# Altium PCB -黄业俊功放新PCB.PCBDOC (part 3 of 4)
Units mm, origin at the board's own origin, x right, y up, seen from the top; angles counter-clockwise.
Board outline 130 x 100.6 mm, 2 copper layers (Top Layer, Bottom Layer); 47 components, 24 nets, 117 pads, 4 vias.
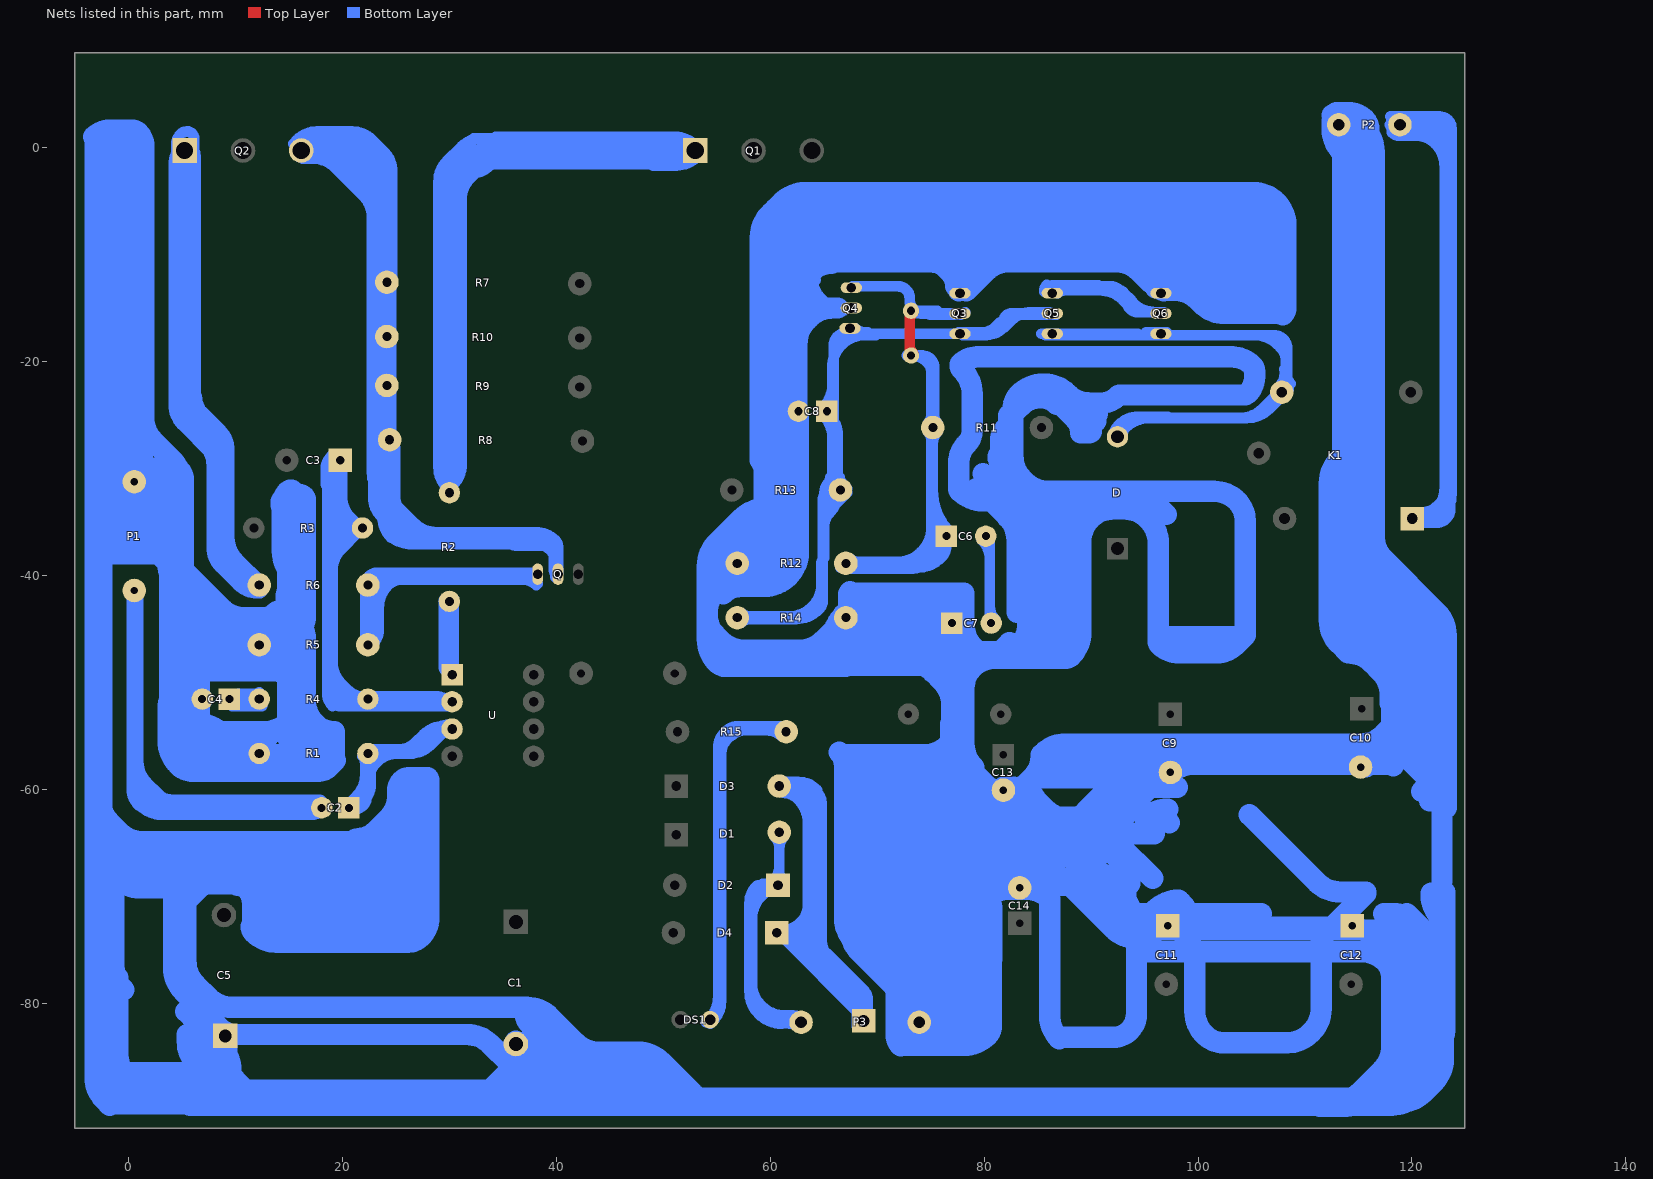
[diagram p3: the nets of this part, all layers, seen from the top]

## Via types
v1: diameter 2.54, hole 0.762, Top Layer to Bottom Layer, 4 vias

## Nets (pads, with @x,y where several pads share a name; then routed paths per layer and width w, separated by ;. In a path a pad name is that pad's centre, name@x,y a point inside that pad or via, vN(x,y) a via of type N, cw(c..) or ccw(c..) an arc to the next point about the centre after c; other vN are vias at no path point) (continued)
GND: (continued)
  Bottom Layer w2: 78.251,-11.434 cw(c81.044,-12.7) 78.582,-10.873 ; 78.251,-11.434 cw(c80.177,-12.954) 78.442,-11.22 78.731,-10.931 cw(c80.899,-13.099) 78.909,-10.766 ; 78.582,-10.873 ccw(c77.798,-7.909) 78.909,-10.766 ; 78.909,-10.766 cw(c80.899,-13.099) 79.788,-10.241 ; 78.909,-10.766 ccw(c77.798,-7.909) 79.788,-10.241 ; 79.788,-10.241 cw(c80.899,-13.099) 80.085,-10.143 ; C13.2@81.788,-60.225 cw(c81.788,-57.837) 80.1,-59.526 ccw(c81.788,-57.837) C13.2@81.788,-60.225 ; 83.058,-67.183 ccw(c81.525,-65.65) 83.595,-66.294 ccw(c81.525,-65.65) 83.63,-66.167 ccw(c81.525,-65.65) 83.654,-66.058 ; 83.058,-67.183 83.058,-65.733 ccw(c83.238,-65.733) 83.111,-65.86 ccw(c83.544,-66.294) 83.058,-65.92 ccw(c83.544,-66.294) 82.931,-66.294 ccw(c82.931,-65.068) 83.058,-66.287 ccw(c82.931,-65.068) 83.474,-66.167 ccw(c82.931,-65.068) 83.654,-66.058 ; 85.874,-62.472 ccw(c87.757,-60.053) 86.535,-62.865 ccw(c87.757,-60.053) 87.06,-63.039 ; 85.874,-62.472 ccw(c87.122,-59.672) 87.122,-62.738 90.17,-62.738 ccw(c90.17,-59.672) 90.178,-62.738 ; 86.006,-62.348 ccw(c87.249,-59.545) 86.969,-62.598 ; 86.006,-62.348 ccw(c87.503,-59.672) 87.458,-62.738 ; 86.931,-63.213 ccw(c88.011,-63.881) 86.767,-63.627 ccw(c88.011,-63.881) 86.741,-63.881 88.138,-63.881 ccw(c88.138,-60.815) 89.024,-63.75 ; 86.931,-63.213 cw(c88.011,-63.881) 86.995,-63.119 cw(c88.011,-63.881) 87.06,-63.039 ; 86.931,-63.213 ccw(c87.376,-60.18) 87.376,-63.246 88.9,-63.246 ccw(c88.9,-60.18) 88.921,-63.246 ; 86.969,-62.598 ccw(c87.249,-59.545) 87.249,-62.611 91.44,-62.611 ; 86.969,-62.598 ccw(c87.884,-59.672) 87.508,-62.715 ; 87.458,-62.738 cw(c88.011,-63.881) 87.508,-62.715 ; 87.508,-62.715 ccw(c87.884,-59.672) 87.884,-62.738 ccw(c87.884,-60.285) 88.663,-62.611 ccw(c87.884,-60.285) 88.711,-62.594 ; 88.711,-62.594 ccw(c88.392,-59.545) 89.178,-62.509 ; 88.711,-62.594 ccw(c87.884,-60.285) 89.313,-62.279 ; 88.921,-63.246 ccw(c88.9,-60.18) 89.773,-63.119 ccw(c88.9,-60.18) 90.259,-62.928 ; 88.921,-63.246 ccw(c91.567,-63.754) 88.876,-63.627 ccw(c91.567,-63.754) 88.873,-63.754 ccw(c88.873,-60.688) 89.024,-63.75 ; 88.921,-63.246 cw(c91.567,-63.754) 88.949,-63.119 cw(c91.567,-63.754) 89.024,-62.865 cw(c91.567,-63.754) 89.072,-62.738 cw(c91.567,-63.754) 89.127,-62.611 cw(c91.567,-63.754) 89.178,-62.509 ; 89.024,-63.75 ccw(c88.873,-60.688) 89.746,-63.627 ccw(c88.873,-60.688) 90.75,-63.113 ; 89.024,-63.75 ccw(c88.138,-60.815) 89.36,-63.627 ccw(c88.138,-60.815) 90.161,-63.119 ccw(c88.138,-60.815) 90.306,-62.983 cw(c90.634,-62.655) 90.259,-62.928 ; 89.178,-62.509 cw(c91.567,-63.754) 89.313,-62.279 ; 89.313,-62.279 cw(c91.567,-63.754) 89.662,-61.849 92.828,-58.683 cw(c94.996,-60.851) 92.993,-58.529 ; 90.178,-62.738 ccw(c90.17,-59.672) 90.645,-62.701 ; 90.178,-62.738 ccw(c90.634,-62.655) 90.259,-62.928 ; 90.178,-62.738 cw(c90.634,-62.655) 90.17,-62.655 ccw(c90.17,-60.614) 90.59,-62.611 ccw(c90.17,-60.614) 90.867,-62.532 ; 90.259,-62.928 ccw(c88.9,-60.18) 90.645,-62.701 ; 90.302,-62.515 ccw(c89.535,-61.849) 90.319,-62.495 ; 90.302,-62.515 cw(c89.535,-61.849) 90.207,-62.611 cw(c89.535,-61.849) 90.027,-62.738 cw(c89.535,-61.849) 89.535,-62.865 85.598,-62.865 cw(c85.598,-61.849) 84.582,-61.849 ccw(c85.852,-61.849) 85.852,-63.119 90.551,-63.119 ccw(c90.551,-60.053) 90.75,-63.113 ; 90.319,-62.495 ccw(c89.789,-61.341) 90.889,-61.976 ccw(c89.789,-61.341) 90.953,-61.849 ccw(c89.789,-61.341) 91.059,-61.341 cw(c91.059,-61.849) 91.522,-61.64 cw(c91.059,-61.849) 91.567,-61.849 90.805,-61.849 ccw(c90.805,-61.976) 90.772,-61.853 ; 90.319,-62.495 cw(c89.789,-61.341) 89.789,-62.611 ccw(c89.789,-61.595) 90.369,-62.429 ; 90.319,-62.495 ccw(c89.535,-61.849) 90.369,-62.429 ; 90.369,-62.429 ccw(c89.789,-61.595) 90.731,-61.976 ccw(c89.789,-61.595) 90.772,-61.853 ; 90.369,-62.429 ccw(c89.535,-61.849) 90.551,-61.849 cw(c91.44,-61.849) 90.562,-61.711 cw(c91.44,-61.849) 91.302,-60.971 cw(c91.44,-61.849) 91.44,-60.96 ccw(c91.44,-61.595) 91.297,-60.976 ccw(c91.44,-61.595) 90.821,-61.452 ccw(c91.44,-61.595) 90.805,-61.595 cw(c89.789,-61.595) 90.772,-61.853 ; 90.645,-62.701 ccw(c90.17,-59.672) 91.043,-62.611 ccw(c90.17,-59.672) 91.43,-62.467 ccw(c90.17,-59.672) 91.568,-62.401 ; 90.645,-62.701 ccw(c88.9,-60.18) 90.768,-62.611 ccw(c88.9,-60.18) 90.867,-62.532 ; 90.75,-63.113 ccw(c90.551,-60.053) 92.719,-62.221 95.033,-59.907 cw(c95.25,-60.124) 95.25,-59.817 ; 90.75,-63.113 ccw(c88.873,-60.688) 90.821,-63.055 ; 90.772,-61.853 ccw(c90.805,-61.976) 90.678,-61.976 91.44,-61.976 ccw(c91.44,-60.706) 91.69,-61.951 ; 90.821,-63.055 ccw(c90.424,-61.849) 91.44,-62.611 ; 90.821,-63.055 ccw(c88.873,-60.688) 91.041,-62.856 93.599,-60.298 cw(c92.001,-60.298) 93.559,-60.655 ; 90.867,-62.532 ccw(c90.17,-60.614) 91.613,-62.057 ccw(c91.613,-59.911) 91.677,-62.056 ; 91.186,-64.157 cw(c89.916,-66.947) 91.802,-64.53 ; 91.186,-64.157 ccw(c91.948,-64.135) 91.198,-64.27 ; 91.198,-64.27 ccw(c91.948,-64.135) 91.948,-64.897 cw(c91.948,-66.167) 92.418,-64.987 ; 91.198,-64.27 cw(c90.297,-67.201) 91.802,-64.53 ; 91.44,-62.611 ccw(c91.44,-61.341) 92.622,-61.805 ; 91.44,-62.611 ccw(c90.424,-61.849) 91.568,-62.401 ; 91.568,-62.401 ccw(c90.17,-59.672) 92.191,-61.978 ; 91.568,-62.401 ccw(c90.424,-61.849) 91.62,-62.277 ccw(c90.424,-61.849) 91.677,-62.056 ; 91.677,-62.056 ccw(c91.613,-59.911) 91.854,-62.043 ccw(c91.613,-59.911) 92.191,-61.978 ; 91.677,-62.056 ccw(c90.424,-61.849) 91.69,-61.951 ; 91.69,-61.951 ccw(c91.44,-60.706) 92.115,-61.782 ccw(c91.44,-60.706) 92.516,-61.381 ccw(c91.44,-60.706) 92.606,-61.208 ; 91.69,-61.951 ccw(c90.424,-61.849) 91.694,-61.849 91.694,-61.595 ccw(c91.694,-60.325) 91.828,-61.588 ccw(c91.694,-60.325) 92.606,-61.208 ; 91.802,-64.53 cw(c90.297,-67.201) 92.418,-64.987 ; 92.191,-61.978 ccw(c91.613,-59.911) 92.622,-61.805 ; 92.191,-61.978 ccw(c90.17,-59.672) 92.338,-61.84 93.367,-60.811 cw(c94.234,-61.678) 93.559,-60.655 ; 92.418,-64.987 cw(c91.948,-66.167) 93.127,-65.695 cw(c91.948,-66.167) 93.218,-66.167 93.218,-70.358 ccw(c94.488,-70.358) 93.472,-71.12 ccw(c94.488,-70.358) 93.726,-71.374 ccw(c94.488,-70.358) 94.488,-71.628 ; 92.606,-61.208 ccw(c91.694,-60.325) 92.71,-61.087 ccw(c91.694,-60.325) 92.957,-60.459 ccw(c91.694,-60.325) 92.964,-60.325 92.964,-58.801 cw(c94.234,-58.801) 92.993,-58.529 ; 92.606,-61.208 ccw(c91.44,-60.706) 92.71,-60.706 92.71,-61.341 cw(c91.44,-61.341) 92.703,-61.475 cw(c91.44,-61.341) 92.622,-61.805 ; 92.622,-61.805 ccw(c91.613,-59.911) 93.091,-61.467 ccw(c91.613,-59.911) 93.131,-61.428 ccw(c92.001,-60.298) 93.559,-60.655 ; 92.993,-58.529 cw(c94.996,-60.851) 93.097,-58.444 ; 55.641,-39.482 cw(c56.896,-40.736) 56.896,-38.962 ccw(c56.896,-40.736) 55.641,-39.482 ; R12.2@56.896,-38.762 ccw(c56.896,-36.374) 58.584,-38.063 cw(c56.896,-36.374) R12.2@56.896,-38.762
NetC2_1: C2.1 R1.1 U.3 | length 90.2
  Bottom Layer w1: C2.1@20.447,-61.722 ccw(c20.447,-59.576) 21.965,-61.093 ccw(c20.416,-59.545) 22.606,-59.545 R1.1@22.606,-57.023 ; C2.1@20.447,-61.468 21.308,-60.607 ccw(c19.4,-58.699) 22.098,-58.699 22.098,-58.268 cw(c24.796,-58.268) 22.888,-56.36 24.946,-56.36 ccw(c24.946,-53.662) 26.854,-55.569 27.531,-54.892 cw(c29.439,-56.8) 29.439,-54.102 U.3@30.099,-54.102 ; C2.1@20.574,-61.849 21.107,-61.849 ccw(c21.107,-60.731) 22.225,-60.731 22.225,-56.515 26.441,-56.515 ccw(c26.441,-55.397) 27.559,-55.397 cw(c28.6,-55.397) 28.6,-54.356 U.3@30.226,-54.356 ; C2.1@21.209,-61.341 21.308,-61.242 ccw(c19.4,-59.334) 22.098,-59.334 22.098,-57.509 ccw(c21.231,-57.509) 21.844,-56.896 21.918,-56.822 ccw(c21.485,-56.388) 22.098,-56.388 cw(c21.791,-56.695) R1.1@22.225,-56.695 ; R1.1@21.971,-56.515 25.298,-56.515 ccw(c25.298,-53.817) 27.206,-55.725 27.912,-55.019 cw(c29.82,-56.927) 29.82,-54.229 U.3@30.099,-54.229 ; 22.352,-59.411 cw(c25.05,-59.411) 23.142,-57.503 23.213,-57.432 cw(c25.121,-59.34) 25.121,-56.642 26.314,-56.642 ; 22.352,-59.309 22.352,-58.903 cw(c25.05,-58.903) 23.142,-56.995 cw(c23.994,-57.846) 23.994,-56.642 26.543,-56.642 27.671,-55.514 ; R1.1@22.606,-56.261 25.171,-56.261 ccw(c25.171,-53.563) 27.079,-55.471 27.559,-54.991 cw(c29.092,-56.524) 29.092,-54.356 U.3@29.718,-54.356 ; R1.1@22.86,-56.642 26.314,-56.642 ; 26.168,-56.255 cw(c27.686,-57.772) 27.686,-55.626 ; 28.238,-54.693 cw(c29.972,-56.428) U.3@29.972,-53.975 ; 28.417,-54.768 cw(c29.718,-56.069) U.3@29.718,-54.229 ; 28.531,-54.781 cw(c29.556,-55.806) 29.556,-54.356 U.3@30.099,-54.356 ; U.3@29.845,-54.229 28.222,-55.852 ; U.3@30.353,-54.483 ccw(c30.353,-56.323) 29.052,-55.022 28.222,-55.852 ; 26.314,-56.642 ccw(c26.314,-53.944) 28.222,-55.852 ; 26.314,-56.642 ccw(c26.314,-53.944) 28.222,-55.852
NetC2_2: C2.2 P1.2 | length 212.5
  Bottom Layer w1: P1.2@0.254,-41.656 0.254,-59.935 ccw(c2.422,-59.935) 0.889,-61.468 ; P1.2@0.508,-41.402 0.508,-60.604 ccw(c1.626,-60.604) 1.626,-61.722 17.78,-61.722 ccw(c17.78,-61.468) C2.2@18.034,-61.468 ; 0.635,-58.039 0.635,-59.207 ccw(c3.333,-59.207) 1.425,-61.115 1.561,-61.251 ccw(c1.778,-61.034) 1.778,-61.341 ; P1.2@0.635,-41.783 cw(c0.328,-42.09) 0.762,-42.09 0.762,-57.683 ccw(c3.46,-57.683) 1.552,-59.591 2.131,-60.17 ccw(c4.039,-58.262) 4.039,-60.96 17.727,-60.96 cw(c17.727,-61.394) C2.2@18.034,-61.087 ; P1.2@0.635,-41.529 0.635,-58.064 ccw(c3.333,-58.064) 1.425,-59.972 2.131,-60.678 ccw(c4.039,-58.77) 4.039,-61.468 11.684,-61.468 ; 0.889,-61.087 ccw(c1.502,-61.087) 1.069,-61.521 1.115,-61.567 ccw(c3.023,-59.659) 3.023,-62.357 17.114,-62.357 ccw(c17.114,-61.056) C2.2@18.034,-61.976 ; 16.383,-61.214 4.674,-61.214 cw(c4.674,-58.516) 2.766,-60.424 1.679,-59.337 cw(c3.587,-57.429) 0.889,-57.429 0.889,-42.576 ccw(c-0.412,-42.576) 0.508,-41.656 0.508,-58.191 ccw(c3.206,-58.191) 1.298,-60.099 1.623,-60.424 ccw(c3.531,-58.516) 3.531,-61.214 C2.2@18.034,-61.214
NetC3_1: C3.1 R3.1 R4.2 U.2 | length 215.3
  Bottom Layer w1: 18.415,-31.496 18.415,-30.055 cw(c20.149,-30.055) 18.923,-28.829 ccw(c19.536,-28.216) 19.536,-29.083 19.536,-32.262 ccw(c22.234,-32.262) 20.326,-34.169 R3.1@21.463,-35.306 ; 18.542,-50.927 19.022,-51.407 ccw(c20.93,-49.499) 20.93,-52.197 U.2@30.099,-52.197 ; 18.542,-49.911 18.542,-50.971 ccw(c20.276,-50.971) 19.05,-52.197 ; 18.669,-35.687 18.895,-35.461 ccw(c16.987,-33.553) 19.685,-33.553 C3.1@19.685,-29.083 ; 18.796,-39.243 18.796,-39.218 cw(c21.494,-39.218) 19.586,-37.31 R3.1@21.336,-35.56 ; 18.796,-36.957 18.796,-31.05 cw(c21.398,-31.05) C3.1@19.558,-29.21 ; 18.923,-49.911 18.923,-50.515 ccw(c20.224,-50.515) 19.304,-51.435 ccw(c19.917,-50.822) 19.917,-51.689 24.257,-51.689 ; 19.177,-50.292 cw(c18.87,-50.599) 19.304,-50.599 19.304,-51.054 ccw(c21.144,-49.214) 21.144,-51.816 U.2@30.48,-51.816 ; C3.1@19.177,-29.337 19.177,-32.664 ccw(c21.875,-32.664) 19.967,-34.572 20.32,-34.925 ; C3.1@19.304,-29.464 ccw(c21.144,-31.304) 18.542,-31.304 18.542,-50.292 ccw(c20.995,-50.292) 19.26,-52.026 ccw(c19.672,-51.615) 19.672,-52.197 23.876,-52.197 ; C3.1@19.558,-29.591 19.558,-33.339 ccw(c22.16,-33.339) 20.32,-35.179 R3.1@21.59,-35.179 ; C3.1@19.939,-29.337 19.939,-32.664 ccw(c22.637,-32.664) 20.729,-34.572 R3.1@21.59,-35.433 ; 20.193,-35.306 19.713,-35.786 ccw(c21.621,-37.694) 18.923,-37.694 18.923,-48.285 ccw(c21.621,-48.285) 19.713,-50.193 20.292,-50.772 ccw(c22.2,-48.864) 22.2,-51.562 28.829,-51.562 ; 20.828,-51.308 28.64,-51.308 cw(c28.64,-53.91) U.2@30.48,-52.07 ; R3.1@21.082,-35.179 ccw(c21.082,-37.325) 19.564,-35.808 19.459,-35.913 ccw(c21.367,-37.821) 18.669,-37.821 18.669,-49.047 ccw(c21.367,-49.047) 19.459,-50.955 ccw(c21.231,-49.184) 21.231,-51.689 R4.2@22.606,-51.689 ; R3.1@21.463,-35.941 19.84,-37.564 ccw(c21.748,-39.472) 19.05,-39.472 19.05,-48.158 ccw(c21.748,-48.158) 19.84,-50.066 20.419,-50.645 ccw(c22.327,-48.737) 22.327,-51.435 R4.2@22.479,-51.435 ; R4.2@21.971,-51.562 19.66,-51.562 cw(c19.66,-50.444) 18.542,-50.444 18.542,-36.297 cw(c19.66,-36.297) 19.66,-35.179 R3.1@22.098,-35.179 ; R4.2@22.225,-51.562 30.226,-51.562 cw(c30.226,-51.943) U.2@30.607,-51.943
NetC4_1: C4.1 R4.1 | length 13.3
  Bottom Layer w1: C4.1@9.398,-51.562 11.938,-51.562 ccw(c11.938,-51.435) R4.1@12.065,-51.435 ; C4.1@9.652,-51.689 11.272,-51.689 cw(c11.272,-52.99) 12.192,-52.07 12.192,-50.927 cw(c11.885,-50.62) 11.885,-51.054 10.287,-51.054 10.011,-51.33 ccw(c10.878,-52.197) 9.652,-52.197 12.446,-52.197 12.446,-51.869 ccw(c12.012,-51.869) R4.1@12.319,-51.562
NetC6_1: C6.1 pad.0@73.152,-15.24 pad.1@73.152,-19.431 Q3.2 Q4.1 R11.1 R12.1 | length 224.7
  Top Layer w1: pad.1@73.025,-19.558 73.025,-15.494 cw(c73.279,-15.494) pad.0@73.279,-15.24 ; 73.025,-18.492 ccw(c74.091,-18.492) pad.1@73.337,-19.246 ; 73.025,-18.492 ccw(c74.091,-18.492) pad.1@73.337,-19.246 ; 73.025,-18.492 ccw(c74.091,-18.492) pad.1@73.337,-19.246 ; 73.025,-18.492 ccw(c74.091,-18.492) pad.1@73.337,-19.246 ; 73.025,-18.492 ccw(c74.091,-18.492) pad.1@73.337,-19.246 ; 73.025,-16.179 cw(c74.091,-16.179) pad.0@73.337,-15.425 ; 73.025,-16.179 cw(c74.091,-16.179) pad.0@73.337,-15.425 ; 73.025,-16.179 cw(c74.091,-16.179) pad.0@73.337,-15.425 ; 73.025,-16.179 cw(c74.091,-16.179) pad.0@73.337,-15.425 ; 73.025,-16.179 cw(c74.091,-16.179) pad.0@73.337,-15.425
  Bottom Layer w1: R12.1@66.548,-39.243 73.787,-39.243 ccw(c73.787,-36.177) 75.27,-38.86 ccw(c73.787,-36.177) 75.955,-38.345 ccw(c74.75,-37.14) 76.326,-37.788 ccw(c74.75,-37.14) 76.454,-37.14 C6.1@76.454,-36.068 ; R12.1@66.802,-39.243 ccw(c67.109,-38.936) 67.109,-39.37 73.025,-39.37 ccw(c73.025,-36.304) 75.193,-38.472 75.565,-38.1 ; R12.1@66.802,-38.735 71.882,-38.735 ccw(c71.882,-35.669) 74.05,-37.837 C6.1@75.692,-36.195 ; R12.1@67.056,-38.735 73.979,-38.735 ccw(c73.979,-36.133) 75.819,-37.973 cw(c76.126,-37.666) 75.692,-37.666 75.692,-35.052 ccw(c76.462,-35.052) C6.1@76.457,-35.822 ; Q4.1@67.691,-12.954 71.907,-12.954 cw(c71.907,-14.072) 73.025,-14.072 73.025,-14.249 ccw(c74.143,-14.249) pad.0@73.625,-15.24 ; 69.731,-39.37 cw(c69.731,-36.187) R12.1@67.48,-38.438 ; 70.231,-39.37 71.247,-39.37 ccw(c71.247,-36.304) 73.415,-38.472 74.159,-37.728 ccw(c71.991,-35.56) 75.057,-35.56 R11.1@75.057,-25.908 ; pad.1@72.771,-19.431 74.193,-19.431 cw(c74.193,-20.549) 75.311,-20.549 R11.1@75.311,-26.289 ; pad.0@72.898,-15.24 75.597,-15.24 ccw(c75.851,-15.24) 75.851,-15.494 77.851,-15.494 cw(c77.724,-15.494) 77.724,-15.621 74.93,-15.621 ; pad.1@73.152,-19.431 cw(c73.152,-21.577) 74.67,-20.06 cw(c73.734,-20.995) 75.057,-20.995 R11.1@75.057,-25.654 ; pad.0@73.152,-15.113 ccw(c74.072,-14.193) 74.072,-15.494 ; pad.1@73.279,-19.431 cw(c73.279,-21.884) 75.013,-20.149 cw(c74.295,-20.868) 75.311,-20.868 R11.1@75.311,-25.4 ; pad.0@73.376,-15.103 ccw(c74.072,-14.678) 74.072,-15.494 ; 74.083,-37.804 cw(c76.454,-40.175) C6.1@76.454,-36.822 ; 74.398,-15.494 cw(c74.398,-13.994) pad.0@73.337,-15.055 ; 74.422,-38.735 ccw(c72.276,-36.589) 75.311,-36.589 75.311,-35.56 ; 75.057,-34.156 ccw(c78.62,-34.156) C6.1@76.1,-36.676 ; 75.057,-31.742 ccw(c81.034,-31.742) C6.1@76.808,-35.968 ; 75.057,-27.917 cw(c76.939,-27.917) R11.1@75.608,-26.586 ; 75.057,-27.304 ccw(c74.042,-27.304) R11.1@74.76,-26.586 ; 75.057,-25.02 cw(c74.042,-25.02) R11.1@74.76,-25.738 ; 75.057,-24.407 ccw(c76.939,-24.407) R11.1@75.608,-25.738 ; R11.1@75.184,-26.162 75.184,-35.077 ccw(c76.302,-35.077) C6.1@76.302,-36.195 ; 75.692,-37.867 cw(c76.769,-37.867) C6.1@76.554,-36.812 ; Q3.2@77.343,-15.494 74.072,-15.494 ; R12.1@67.48,-39.286 cw(c68.811,-40.617) 68.811,-38.735 ccw(c68.811,-40.617) R12.1@67.48,-39.286 ; R12.1@67.48,-39.286 cw(c68.505,-40.311) 68.505,-38.862 ; R12.1@67.48,-39.286 cw(c68.505,-40.311) 68.505,-38.862 ; R12.1@67.48,-39.286 cw(c68.505,-40.311) 68.505,-38.862 ; R12.1@67.48,-38.438 ccw(c68.198,-37.72) 68.198,-38.735 cw(c68.198,-37.72) R12.1@67.48,-38.438 ; R12.1@67.48,-38.438 ccw(c69.424,-36.494) 69.424,-39.243 cw(c69.424,-36.494) R12.1@67.48,-38.438 ; R12.1@67.48,-38.438 ccw(c68.505,-37.413) 68.505,-38.862 ; R12.1@67.48,-38.438 ccw(c68.505,-37.413) 68.505,-38.862 ; R12.1@67.48,-38.438 ccw(c68.505,-37.413) 68.505,-38.862 ; 73.025,-14.301 ccw(c74.091,-14.301) pad.0@73.337,-15.055 ; 73.025,-14.301 ccw(c74.091,-14.301) pad.0@73.337,-15.055 ; 73.025,-14.301 ccw(c74.091,-14.301) pad.0@73.337,-15.055 ; 73.025,-14.301 ccw(c74.091,-14.301) pad.0@73.337,-15.055 ; 73.025,-14.301 ccw(c74.091,-14.301) pad.0@73.337,-15.055 ; 73.025,-14.301 ccw(c74.091,-14.301) pad.0@73.337,-15.055 ; 73.025,-14.301 ccw(c74.091,-14.301) pad.0@73.337,-15.055 ; 73.025,-14.301 ccw(c74.091,-14.301) pad.0@73.337,-15.055 ; 73.025,-14.301 ccw(c74.091,-14.301) pad.0@73.337,-15.055 ; 73.025,-14.301 ccw(c74.091,-14.301) pad.0@73.337,-15.055 ; R11.1@74.76,-26.586 cw(c73.735,-27.611) 75.184,-27.611 ; R11.1@74.76,-26.586 cw(c73.735,-27.611) 75.184,-27.611 ; R11.1@74.76,-25.738 ccw(c73.429,-24.407) 75.311,-24.407 ; R11.1@74.76,-25.738 ccw(c73.429,-24.407) 75.311,-24.407 ; R11.1@74.76,-25.738 ccw(c73.429,-24.407) 75.311,-24.407 ; 75.184,-34.463 ccw(c78.313,-34.463) C6.1@76.1,-36.676 ; 75.184,-34.463 ccw(c78.313,-34.463) C6.1@76.1,-36.676 ; 75.184,-34.463 ccw(c78.313,-34.463) C6.1@76.1,-36.676 ; 75.184,-34.463 ccw(c78.313,-34.463) C6.1@76.1,-36.676 ; 75.184,-34.463 ccw(c78.313,-34.463) C6.1@76.1,-36.676 ; 75.184,-32.049 ccw(c80.727,-32.049) C6.1@76.808,-35.968 ; 75.184,-32.049 ccw(c80.727,-32.049) C6.1@76.808,-35.968 ; 75.184,-32.049 ccw(c80.727,-32.049) C6.1@76.808,-35.968 ; 75.184,-32.049 ccw(c80.727,-32.049) C6.1@76.808,-35.968 ; 75.184,-32.049 ccw(c80.727,-32.049) C6.1@76.808,-35.968 ; 75.184,-27.611 cw(c76.633,-27.611) R11.1@75.608,-26.586 ; 75.184,-27.611 cw(c76.633,-27.611) R11.1@75.608,-26.586 ; 75.311,-25.02 ccw(c76.326,-25.02) R11.1@75.608,-25.738 ; 75.311,-25.02 ccw(c76.326,-25.02) R11.1@75.608,-25.738 ; 75.311,-25.02 ccw(c76.326,-25.02) R11.1@75.608,-25.738 ; 76.327,-37.75 cw(c77.767,-37.75) C6.1@76.792,-36.69 ; 76.327,-37.75 cw(c77.767,-37.75) C6.1@76.792,-36.69 ; 76.327,-37.75 cw(c77.767,-37.75) C6.1@76.792,-36.69
NetC6_2: C6.2 C7.2 | length 19.9
  Bottom Layer w1: C6.2@79.883,-36.195 cw(c79.883,-36.83) 80.518,-36.83 C7.2@80.518,-44.577 ; 80.518,-42.936 ccw(c82.159,-42.936) C7.2@80.999,-44.096 ; C6.2@79.783,-36.676 cw(c78.01,-38.449) 80.518,-38.449 ; C6.2@79.783,-36.676 cw(c78.01,-38.449) 80.518,-38.449 ; C6.2@79.783,-36.676 cw(c78.01,-38.449) 80.518,-38.449 ; C6.2@79.783,-36.676 cw(c78.01,-38.449) 80.518,-38.449 ; C6.2@79.783,-36.676 cw(c78.01,-38.449) 80.518,-38.449
NetC8_1: C8.1 Q3.3 Q4.3 Q5.2 R13.2 R14.1 | length 216.3
  Bottom Layer w1: R14.1@56.769,-43.815 63.627,-43.815 ; R14.1@56.896,-44.069 62.357,-44.069 ccw(c62.357,-41.003) 64.525,-43.171 ccw(c63.627,-42.273) 64.897,-42.273 64.897,-33.528 ; R14.1@56.896,-43.942 61.849,-43.942 ccw(c61.849,-40.876) 64.017,-43.044 ccw(c61.893,-40.92) 64.897,-40.92 64.897,-38.862 64.897,-37.084 ; 60.325,-43.815 61.874,-43.815 ccw(c61.874,-41.117) 63.782,-43.025 63.98,-42.827 ccw(c62.072,-40.919) 64.77,-40.919 64.77,-38.945 cw(c65.637,-38.945) 65.024,-38.332 ; 64.897,-42.545 64.897,-33.02 cw(c66.167,-33.02) 66.04,-31.756 cw(c66.167,-33.02) 66.167,-31.75 66.294,-31.75 cw(c66.294,-31.369) 66.04,-31.653 cw(c66.294,-31.369) 65.913,-31.369 65.913,-18.542 cw(c67.183,-18.542) 66.04,-17.988 cw(c67.183,-18.542) 67.142,-17.273 cw(c67.183,-18.542) 67.183,-17.272 69.088,-17.272 ; 64.897,-35.687 64.897,-33.655 cw(c67.963,-33.655) 65.795,-31.487 R13.2@66.167,-31.115 ; 65.024,-35.687 65.024,-35.535 cw(c67.722,-35.535) 65.814,-33.627 R13.2@67.183,-32.258 ; 65.278,-33.147 cw(c67.424,-33.147) 65.907,-31.629 R13.2@66.294,-31.242 ; C8.1@65.278,-24.765 65.504,-24.991 cw(c63.596,-26.899) 66.294,-26.899 66.294,-32.283 cw(c63.596,-32.283) 65.504,-34.191 ccw(c66.662,-35.349) 65.024,-35.349 65.024,-38.332 ; 65.786,-29.18 ccw(c68.102,-29.18) 66.464,-30.818 ; 65.786,-27.072 ccw(c62.844,-27.072) C8.1@64.924,-24.992 ; 65.786,-22.204 cw(c62.844,-22.204) C8.1@64.924,-24.284 ; 66.167,-28.067 66.167,-29.743 ccw(c68.865,-29.743) 66.957,-31.651 R13.2@67.183,-31.877 ; 69.088,-17.399 80.67,-17.399 ccw(c80.67,-16.281) 81.788,-16.281 cw(c82.575,-16.281) 82.575,-15.494 Q5.2@86.233,-15.494 ; 69.85,-17.526 68.834,-17.526 ccw(c68.834,-20.592) 66.666,-18.424 ccw(c68.79,-20.548) 65.786,-20.548 65.786,-30.681 cw(c65.352,-30.681) 65.659,-30.988 ccw(c67.192,-32.521) 65.024,-32.521 65.024,-38.332 ; Q3.3@77.597,-17.272 79.8,-17.272 ccw(c79.8,-15.538) 81.026,-16.764 81.271,-16.519 cw(c83.439,-18.687) 83.439,-15.621 Q5.2@86.741,-15.621 ; Q3.3@77.978,-17.526 79.883,-17.526 ccw(c79.883,-14.46) 82.051,-16.628 82.55,-16.129 cw(c84.39,-17.969) 84.39,-15.367 Q5.2@86.106,-15.367 ; R14.1@57.32,-44.366 cw(c58.651,-45.697) 58.651,-43.815 ccw(c58.651,-45.697) R14.1@57.32,-44.366 ; R14.1@57.32,-44.366 cw(c58.038,-45.084) 58.038,-44.069 ; R14.1@57.32,-44.366 cw(c58.345,-45.391) 58.345,-43.942 cw(c58.345,-42.493) R14.1@57.32,-43.518 ; R14.1@57.32,-44.366 cw(c58.038,-45.084) 58.038,-44.069 ; R14.1@57.32,-44.366 cw(c58.038,-45.084) 58.038,-44.069 ; R14.1@57.32,-44.366 cw(c58.038,-45.084) 58.038,-44.069 ; R14.1@57.32,-43.518 ccw(c58.038,-42.8) 58.038,-43.815 cw(c58.038,-42.8) R14.1@57.32,-43.518 ; R14.1@57.32,-43.518 ccw(c58.651,-42.187) 58.651,-44.069 ; R14.1@57.32,-43.518 ccw(c58.651,-42.187) 58.651,-44.069 ; R14.1@57.32,-43.518 ccw(c58.651,-42.187) 58.651,-44.069 ; R14.1@57.32,-43.518 ccw(c58.651,-42.187) 58.651,-44.069 ; C8.1@64.924,-24.992 cw(c62.538,-27.378) 65.913,-27.378 ccw(c62.538,-27.378) C8.1@64.924,-24.992 ; C8.1@64.924,-24.284 ccw(c62.538,-21.898) 65.913,-21.898 cw(c62.538,-21.898) C8.1@64.924,-24.284 ; 65.616,-30.818 ccw(c64.898,-30.1) 65.913,-30.1 cw(c64.898,-30.1) 65.616,-30.818 ; 65.616,-30.818 ccw(c64.591,-29.793) 66.04,-29.793 ; 65.616,-30.818 ccw(c64.591,-29.793) 66.04,-29.793 ; 65.616,-30.818 ccw(c64.591,-29.793) 66.04,-29.793 ; 66.04,-29.793 ccw(c67.489,-29.793) 66.464,-30.818 ; 66.04,-29.793 ccw(c67.489,-29.793) 66.464,-30.818 ; 66.04,-29.793 ccw(c67.489,-29.793) 66.464,-30.818 ; 66.464,-30.818 cw(c67.795,-29.487) 65.913,-29.487 ccw(c67.795,-29.487) 66.464,-30.818 ; Q4.3@67.937,-16.891 ccw(c68.857,-15.971) 68.857,-17.272 cw(c68.857,-15.971) Q4.3@67.937,-16.891 ; Q4.3@67.937,-16.891 ccw(c69.163,-15.665) 69.163,-17.399 ; Q4.3@67.937,-16.891 ccw(c69.163,-15.665) 69.163,-17.399 ; Q4.3@67.937,-16.891 ccw(c69.163,-15.665) 69.163,-17.399
NetD1_1: D1.1 D2.2 P3.3 | length 104.7
  Bottom Layer w1: 58.039,-76.835 58.039,-78.486 ccw(c61.105,-78.486) 58.937,-80.654 59.173,-80.89 ccw(c61.341,-78.722) 61.341,-81.788 ; 58.039,-76.581 58.039,-77.851 ccw(c61.105,-77.851) 58.937,-80.019 59.935,-81.017 ccw(c62.103,-78.849) P3.3@62.103,-81.915 ; 58.039,-73.787 58.039,-72.009 cw(c61.105,-72.009) 58.937,-69.841 59.585,-69.193 cw(c60.452,-70.06) D2.2@60.452,-68.834 ; 58.293,-74.295 58.293,-78.297 ccw(c60.895,-78.297) 59.055,-80.137 59.789,-80.871 ccw(c61.697,-78.963) 61.697,-81.661 ; 59.14,-69.638 cw(c59.874,-70.371) D2.2@60.401,-69.478 ; 59.532,-69.627 cw(c60.833,-70.928) D2.2@60.833,-69.088 ; D2.2@60.579,-68.58 59.101,-70.058 ccw(c61.052,-72.009) 58.293,-72.009 58.293,-77.089 ccw(c58.6,-77.396) 58.166,-77.396 58.166,-77.978 ccw(c61.232,-77.978) 59.064,-80.146 59.173,-80.255 ccw(c61.341,-78.087) 61.341,-81.153 62.072,-81.153 cw(c62.072,-82.454) 62.992,-81.534 63.156,-81.698 cw(c62.939,-81.915) 63.246,-81.915 ccw(c63.246,-82.222) P3.3@63.029,-82.005 ; D2.2@60.706,-68.961 58.981,-68.961 ccw(c58.981,-69.395) 58.674,-69.088 ccw(c60.207,-70.621) 58.039,-70.621 58.039,-78.893 ccw(c61.043,-78.893) 58.166,-79.757 ccw(c61.043,-78.893) 58.293,-80.102 ccw(c61.043,-78.893) 58.919,-81.017 ccw(c61.087,-78.849) 61.087,-81.915 ; D2.2@60.833,-68.834 D1.1@60.833,-64.008 ; 59.257,-68.961 cw(c59.257,-70.41) 60.282,-69.385 ccw(c59.257,-70.41) 59.257,-68.961 ; 59.257,-68.961 ccw(c59.257,-67.512) D2.2@60.282,-68.537 ; 59.257,-68.961 ccw(c59.257,-67.512) D2.2@60.282,-68.537 ; 59.284,-68.834 cw(c59.284,-69.989) D2.2@60.22,-69.312 ; 59.284,-68.834 cw(c59.284,-69.989) D2.2@60.22,-69.312 ; 59.284,-68.834 cw(c59.284,-69.989) D2.2@60.22,-69.312 ; 59.564,-68.834 ccw(c59.564,-67.819) D2.2@60.282,-68.537 ; 59.564,-68.834 ccw(c59.564,-67.819) D2.2@60.282,-68.537 ; 59.564,-68.834 ccw(c59.564,-67.819) D2.2@60.282,-68.537 ; D2.2@60.282,-68.537 ccw(c58.951,-67.206) 60.833,-67.206 ; D2.2@60.282,-68.537 ccw(c58.951,-67.206) 60.833,-67.206 ; D2.2@60.282,-68.537 ccw(c58.951,-67.206) 60.833,-67.206 ; D2.2@60.282,-68.537 ccw(c58.951,-67.206) 60.833,-67.206 ; D2.2@60.282,-68.537 ccw(c58.951,-67.206) 60.833,-67.206 ; D1.1@60.409,-64.432 cw(c59.384,-65.457) 60.833,-65.457 ; D1.1@60.409,-64.432 cw(c59.384,-65.457) 60.833,-65.457 ; D1.1@60.409,-64.432 cw(c59.384,-65.457) 60.833,-65.457 ; D1.1@60.409,-64.432 cw(c59.384,-65.457) 60.833,-65.457 ; D1.1@60.409,-64.432 cw(c59.384,-65.457) 60.833,-65.457 ; 60.833,-67.819 ccw(c61.848,-67.819) D2.2@61.13,-68.537 ; 60.833,-67.819 ccw(c61.848,-67.819) D2.2@61.13,-68.537 ; 60.833,-67.819 ccw(c61.848,-67.819) D2.2@61.13,-68.537 ; 60.833,-67.819 ccw(c61.848,-67.819) D2.2@61.13,-68.537 ; 60.833,-67.819 ccw(c61.848,-67.819) D2.2@61.13,-68.537 ; 60.833,-65.457 cw(c62.282,-65.457) D1.1@61.257,-64.432 ; 60.833,-65.457 cw(c62.282,-65.457) D1.1@61.257,-64.432 ; 60.833,-65.457 cw(c62.282,-65.457) D1.1@61.257,-64.432 ; 60.833,-65.457 cw(c62.282,-65.457) D1.1@61.257,-64.432 ; 60.833,-65.457 cw(c62.282,-65.457) D1.1@61.257,-64.432
NetD3_1: D3.1 D4.2 P3.1 | length 234.4
  Bottom Layer w1: D4.2@60.198,-73.66 60.858,-73.66 cw(c60.858,-76.358) 62.766,-74.45 65.061,-76.745 ; D4.2@60.198,-73.533 61.112,-73.533 cw(c61.112,-76.231) 63.02,-74.323 63.776,-75.079 ccw(c64.643,-74.212) 64.643,-75.438 ; D4.2@60.325,-73.279 63.119,-73.279 cw(c63.119,-74.549) 63.516,-73.343 cw(c63.119,-74.549) 64.262,-73.995 ; D4.2@60.452,-73.787 62.348,-73.787 ; D4.2@60.452,-73.279 60.706,-73.279 ccw(c60.706,-70.213) 62.874,-72.381 ccw(c61.363,-70.87) 63.5,-70.87 63.5,-63.119 ccw(c60.434,-63.119) 62.602,-60.951 62.515,-60.864 ccw(c61.214,-62.165) 61.214,-60.325 D3.1@60.579,-59.69 ; D4.2@60.706,-73.66 61.874,-73.66 cw(c61.874,-76.358) 63.782,-74.45 65.123,-75.791 ; D3.1@60.833,-59.563 62.782,-59.563 cw(c62.782,-61.297) 64.008,-60.071 ; D4.2@60.96,-73.533 ccw(c61.267,-73.533) 61.05,-73.75 68.49,-81.19 cw(c68.273,-81.407) P3.1@68.58,-81.407 ; D4.2@60.96,-73.406 ccw(c61.267,-73.099) 61.267,-73.533 62.646,-73.533 ccw(c62.646,-72.697) 63.237,-73.288 ccw(c61.069,-71.12) 64.135,-71.12 64.135,-61.127 ccw(c63.119,-61.127) 63.837,-60.408 ccw(c62.103,-62.143) 62.103,-59.69 cw(c62.103,-58.464) 61.236,-59.331 61.214,-59.309 62.549,-59.309 ; D4.2@61.087,-73.152 62.611,-73.152 cw(c62.611,-74.422) 63.881,-74.422 ; D4.2@61.088,-73.088 ccw(c62.348,-72.302) 62.348,-73.787 ; D3.1@61.214,-60.071 62.125,-60.071 ; D3.1@61.35,-59.994 cw(c62.549,-60.701) 62.549,-59.309 ; D3.1@61.411,-59.529 ccw(c62.125,-59.33) 62.125,-60.071 ; 61.721,-73.533 ccw(c61.721,-74.548) 61.003,-73.83 cw(c62.334,-75.161) 62.334,-73.279 ; 61.721,-73.279 cw(c61.721,-72.264) 61.003,-72.982 ccw(c62.334,-71.651) 62.334,-73.533 ; 61.975,-59.563 cw(c61.975,-58.548) D3.1@61.257,-59.266 ; 62.588,-59.563 ccw(c62.588,-61.445) D3.1@61.257,-60.114 ; 63.246,-59.436 cw(c63.246,-60.356) 63.896,-59.705 cw(c62.401,-61.201) 64.516,-61.201 64.516,-74.308 ccw(c67.551,-74.308) 65.405,-76.454 ; 63.754,-73.025 ccw(c63.141,-72.412) 64.008,-72.412 64.008,-62.611 ccw(c61.555,-62.611) 63.29,-60.877 62.738,-60.325 ccw(c62.125,-60.938) 62.125,-60.071 ; 64.262,-75.184 ccw(c63.036,-73.958) 64.77,-73.958 64.77,-61.245 ccw(c63.469,-61.245) 64.389,-60.325 ccw(c62.856,-61.858) 62.856,-59.69 D3.1@60.833,-59.69 62.992,-59.69 cw(c62.992,-60.96) 64.262,-60.96 64.262,-73.995 ; 64.262,-74.803 64.262,-75.819 ccw(c65.532,-75.819) 65.532,-77.089 ; 64.389,-74.803 64.389,-74.549 ccw(c63.119,-74.549) 64.262,-73.995 ; 64.77,-73.406 64.77,-73.914 ccw(c67.836,-73.914) 65.668,-76.082 ; 64.984,-76.064 64.262,-75.342 ccw(c62.961,-75.342) 63.881,-74.422 ; 65.269,-76.191 cw(c67.393,-74.067) 64.389,-74.067 64.389,-72.136 64.389,-60.071 ccw(c62.549,-61.911) 62.549,-59.309 ; 65.786,-76.962 65.823,-76.999 ccw(c66.04,-76.782) 66.04,-77.089 67.682,-78.731 cw(c65.514,-80.899) 68.58,-80.899 68.58,-81.026 68.58,-80.137 ccw(c65.514,-80.137) 67.682,-77.969 63.627,-73.914 cw(c62.707,-74.834) 64.008,-74.834 64.008,-74.93 cw(c64.008,-77.076) 65.526,-75.559 68.707,-78.74 cw(c67.787,-79.66) 69.088,-79.66 69.088,-81.862 ccw(c69.522,-81.862) 69.215,-82.169 68.072,-82.169 68.072,-81.28 ccw(c65.006,-81.28) 67.174,-79.112 64.779,-76.717 cw(c66.947,-74.549) 63.881,-74.549 63.881,-74.422 ; D3.1@61.257,-60.114 cw(c62.282,-61.139) 62.282,-59.69 ; D3.1@61.257,-60.114 cw(c62.282,-61.139) 62.282,-59.69 ; D3.1@61.257,-60.114 cw(c62.282,-61.139) 62.282,-59.69 ; D3.1@61.257,-60.114 cw(c62.282,-61.139) 62.282,-59.69 ; D3.1@61.257,-60.114 cw(c62.282,-61.139) 62.282,-59.69 ; D3.1@61.257,-60.114 cw(c62.282,-61.139) 62.282,-59.69 ; D3.1@61.257,-59.266 ccw(c62.282,-58.241) 62.282,-59.69 ; D3.1@61.257,-59.266 ccw(c62.282,-58.241) 62.282,-59.69 ; D3.1@61.257,-59.266 ccw(c62.282,-58.241) 62.282,-59.69 ; D3.1@61.257,-59.266 ccw(c62.282,-58.241) 62.282,-59.69 ; D3.1@61.257,-59.266 ccw(c62.282,-58.241) 62.282,-59.69 ; D3.1@61.257,-59.266 ccw(c62.282,-58.241) 62.282,-59.69 ; 62.348,-73.787 cw(c62.348,-75.955) 63.881,-74.422
NetD_1: D.1 K1.5 Q5.3 Q6.3 | length 149.7
  Bottom Layer w1: 85.344,-17.399 94.361,-17.399 ; Q5.3@85.725,-17.526 Q6.3@96.774,-17.526 ; Q5.3@86.36,-17.526 107.061,-17.526 cw(c107.061,-18.796) 108.331,-18.796 K1.5@108.331,-22.606 ; D.1@92.075,-27.178 cw(c93.915,-27.178) 92.614,-25.877 cw(c94.379,-27.642) 94.379,-25.146 97.155,-25.146 ccw(c97.462,-24.839) 97.462,-25.273 104.521,-25.273 ; D.1@92.202,-27.178 D.1@92.202,-27.028 ; D.1@92.329,-27.051 93.209,-26.171 ; 95.123,-17.272 Q6.3@97.053,-17.272 ; Q6.3@96.266,-17.526 Q6.3@96.266,-17.399 ; 98.171,-25.273 103.886,-25.273 ccw(c103.886,-22.207) 106.054,-24.375 107.755,-22.674 ccw(c106.671,-21.59) 108.204,-21.59 ; 101.346,-17.526 105.283,-17.526 cw(c105.283,-20.592) 107.451,-18.424 107.696,-18.669 cw(c106.47,-19.895) 108.204,-19.895 108.204,-21.59 ; 104.648,-17.526 105.677,-17.526 cw(c105.677,-20.561) 107.823,-18.415 cw(c106.597,-19.641) 108.331,-19.641 108.331,-19.939 ; 106.746,-23.683 cw(c108.204,-25.141) K1.5@108.204,-23.079 ; 107.188,-23.876 107.306,-23.758 ccw(c105.138,-21.59) 108.204,-21.59 ; K1.5@107.379,-23.685 ccw(c106.656,-22.963) K1.5@107.631,-22.658 ; K1.5@107.497,-23.567 ccw(c106.958,-23.029) K1.5@107.655,-22.721 ; K1.5@107.832,-22.008 ccw(c107.016,-20.977) 108.331,-20.977 ; K1.5@108.077,-22.479 108.077,-22.352 K1.5@108.204,-22.352 ; 108.204,-20.32 108.204,-21.59 ; 108.331,-19.05 108.331,-20.977 ; K1.5@108.458,-22.606 106.689,-24.375 cw(c104.521,-22.207) 104.521,-25.273 ; 93.209,-26.171 ccw(c93.857,-26.819) 92.951,-26.954 cw(c93.857,-26.819) 93.209,-26.171 ; 93.209,-26.171 cw(c95.377,-28.339) 95.377,-25.273 104.521,-25.273 ; 104.521,-25.273 ccw(c104.521,-22.514) 106.472,-24.465 107.179,-23.758 ccw(c105.011,-21.59) 108.077,-21.59 ccw(c107.464,-20.977) 108.331,-20.977 ; K1.5@107.78,-22.055 ccw(c106.449,-20.724) 108.331,-20.724 ; K1.5@107.78,-22.055 ccw(c106.755,-21.03) 108.204,-21.03 ; K1.5@107.78,-22.055 ccw(c106.755,-21.03) 108.204,-21.03 ; K1.5@107.78,-22.055 ccw(c106.449,-20.724) 108.331,-20.724 ; K1.5@107.78,-22.055 ccw(c107.062,-21.337) 108.077,-21.337 ; K1.5@107.78,-22.055 ccw(c107.062,-21.337) 108.077,-21.337 ; K1.5@107.78,-22.055 ccw(c107.062,-21.337) 108.077,-21.337 ; K1.5@107.78,-22.055 ccw(c106.449,-20.724) 108.331,-20.724 ; 108.077,-20.724 ccw(c109.959,-20.724) 108.628,-22.055 ; 108.077,-20.724 ccw(c109.959,-20.724) 108.628,-22.055 ; 108.077,-20.724 ccw(c109.959,-20.724) 108.628,-22.055 ; 108.204,-21.03 ccw(c109.653,-21.03) 108.628,-22.055 ; 108.204,-21.03 ccw(c109.653,-21.03) 108.628,-22.055 ; 108.331,-21.337 ccw(c109.346,-21.337) 108.628,-22.055 ; 108.331,-21.337 ccw(c109.346,-21.337) 108.628,-22.055 ; 108.331,-21.337 ccw(c109.346,-21.337) 108.628,-22.055 ; 108.331,-21.337 ccw(c109.346,-21.337) 108.628,-22.055 ; D.1@92.456,-26.528 ccw(c92.456,-25.572) 93.132,-26.248 cw(c92.456,-25.572) D.1@92.456,-26.528 ; 106.91,-24.154 ccw(c105.236,-22.479) 107.604,-22.479 cw(c105.236,-22.479) 106.91,-24.154
NetDS1_1: DS1.1 R15.1 | length 108.9
  Bottom Layer w1: DS1.1@53.975,-81.788 54.22,-81.543 ccw(c52.052,-79.375) 55.118,-79.375 55.118,-75.999 cw(c55.552,-75.999) 55.245,-75.692 ; DS1.1@54.356,-81.915 ccw(c52.516,-80.075) 55.118,-80.075 55.118,-56.143 cw(c57.286,-56.143) 55.753,-54.61 cw(c56.979,-55.836) 56.979,-54.102 61.214,-54.102 R15.1@61.341,-54.102 ; DS1.1@54.61,-81.661 ccw(c52.77,-79.821) 55.372,-79.821 55.372,-57.505 ; 55.372,-70.231 55.372,-56.765 cw(c57.509,-56.765) 55.998,-55.254 cw(c58.166,-57.422) 58.166,-54.356 59.436,-54.356 ; 55.372,-57.658 55.372,-56.459 cw(c57.076,-56.459) 55.871,-55.254 cw(c58.039,-57.422) 58.039,-54.356 R15.1@61.595,-54.356 ; 55.372,-57.023 55.372,-55.753 cw(c56.642,-55.753) 56.642,-54.483 R15.1@61.722,-54.483 ; 56.515,-54.864 56.515,-54.737 ; 58.793,-54.102 cw(c58.793,-57.285) R15.1@61.044,-55.034 ; 59.406,-54.356 cw(c59.406,-56.672) R15.1@61.044,-55.034 ; R15.1@61.044,-55.034 ccw(c59.713,-56.365) 59.713,-54.483 cw(c59.713,-56.365) R15.1@61.044,-55.034 ; 60.326,-54.483 ccw(c60.326,-53.468) 61.044,-54.186 cw(c60.326,-53.468) 60.326,-54.483
NetK1_1: K1.1 P2.1 | length 231.2
  Bottom Layer w1: 117.983,2.921 122.58,2.921 ; P2.1@118.11,2.921 118.11,2.698 ccw(c119.411,2.698) 118.491,1.778 ccw(c118.798,2.085) 118.798,1.651 120.663,1.651 ; P2.1@118.364,2.159 120.917,2.159 cw(c120.917,-0.876) 123.063,1.27 cw(c121.837,0.044) 123.571,0.044 123.571,-33.782 cw(c122.301,-33.782) 122.301,-35.052 ; P2.1@118.364,2.413 121.784,2.413 cw(c121.784,0.245) 123.317,1.778 123.444,1.651 ; P2.1@118.589,2.442 cw(c119.746,1.285) 119.746,2.921 ; P2.1@118.788,2.583 ccw(c119.813,3.608) 119.813,2.159 ccw(c119.813,0.71) P2.1@118.788,1.735 ; P2.1@119.296,2.583 ccw(c120.321,3.608) 120.321,2.159 ccw(c120.321,0.71) P2.1@119.296,1.735 ; P2.1@119.409,2.427 ccw(c120.663,3.052) 120.663,1.651 ; 120.426,2.413 ccw(c120.426,0.097) P2.1@118.788,1.735 ; 120.934,2.413 ccw(c120.934,0.097) P2.1@119.296,1.735 ; K1.1@121.031,-35.052 121.595,-35.052 ccw(c121.595,-33.348) 122.8,-34.553 ccw(c120.632,-32.385) 123.698,-32.385 123.698,-5.334 ; K1.1@121.031,-34.798 122.831,-32.998 ccw(c121.964,-32.131) 123.19,-32.131 123.19,-23.49 ; K1.1@121.031,-34.671 121.044,-34.671 ccw(c121.044,-31.636) 123.19,-33.782 ccw(c122.27,-32.862) 123.571,-32.862 123.571,-28.829 ; 121.158,-34.071 ccw(c121.158,-32.622) 122.182,-33.647 ccw(c123.207,-34.671) 121.758,-34.671 ; 121.285,-35.052 122.301,-35.052 ; 121.285,2.032 120.479,2.032 cw(c120.479,3.766) 119.253,2.54 cw(c118.32,3.473) 118.32,2.153 117.926,2.153 cw(c117.449,1.676) 118.124,1.676 118.124,1.432 ccw(c118.82,2.128) 118.82,1.143 120.347,1.143 cw(c120.347,-1.428) 122.165,0.39 cw(c119.997,-1.778) 123.063,-1.778 123.063,-26.289 ; 121.355,-34.104 ccw(c121.611,-33.364) 122.165,-33.918 ; 121.539,-34.544 122.165,-33.918 ; 122.16,2.921 ccw(c122.16,-1.129) P2.1@119.296,1.735 ; 123.317,-22.076 123.317,-0.464 ccw(c121.583,-0.464) 122.809,0.762 ccw(c120.663,-1.384) 120.663,1.651 ; 123.571,-24.892 cw(c122.345,-24.892) 123.212,-25.759 123.063,-25.908 123.063,-31.75 cw(c119.997,-31.75) 122.165,-33.918 ; 123.698,-6.223 123.698,1.803 ; P2.1@118.081,2.442 cw(c119.238,1.285) P2.1@119.238,2.921 ; P2.1@118.081,2.442 cw(c119.238,1.285) P2.1@119.238,2.921 ; P2.1@118.081,2.442 cw(c119.238,1.285) P2.1@119.238,2.921 ; P2.1@118.081,2.442 cw(c119.238,1.285) P2.1@119.238,2.921 ; P2.1@118.788,1.735 cw(c121.652,-1.129) 121.652,2.921 ; P2.1@118.788,1.735 cw(c121.652,-1.129) 121.652,2.921 ; P2.1@118.788,1.735 cw(c121.652,-1.129) 121.652,2.921 ; P2.1@118.788,1.735 cw(c121.652,-1.129) 121.652,2.921 ; 121.751,-34.58 ccw(c122.301,-34.496) 122.301,-35.052 ; 121.751,-34.58 ccw(c122.301,-34.496) 122.301,-35.052 ; 121.751,-34.58 ccw(c122.301,-34.496) 122.301,-35.052 ; 121.751,-34.58 ccw(c122.301,-34.496) 122.301,-35.052 ; 121.751,-34.58 ccw(c122.301,-34.496) 122.301,-35.052 ; 122.58,2.921 cw(c122.58,1.803) 123.698,1.803 ; 122.58,2.921 cw(c122.58,1.803) 123.698,1.803 ; 122.58,2.921 cw(c122.58,1.803) 123.698,1.803
NetQ1_1: Q1.1 R2.2 | length 420.9
  Bottom Layer w1: 28.956,-6.223 28.956,-3.15 cw(c31.654,-3.15) 29.746,-1.242 31.087,0.099 cw(c32.995,-1.809) 32.995,0.889 39.497,0.889 ; 28.956,-4.953 28.956,-29.87 ccw(c31.654,-29.87) 29.746,-31.778 29.972,-32.004 ccw(c29.052,-31.084) 30.353,-31.084 30.353,-5.69 ; R2.2@29.591,-32.258 30.325,-31.524 ccw(c28.417,-29.616) 31.115,-29.616 31.115,-6.071 ; 29.591,-4.928 29.591,-24.13 cw(c29.284,-24.437) 29.718,-24.437 R2.2@29.718,-32.512 ; 29.718,-28.854 29.718,-4.801 ; 29.718,-17.526 29.718,-32.131 ccw(c29.845,-32.131) R2.2@29.845,-32.258 ; R2.2@29.845,-32.004 ccw(c28.005,-30.164) 30.607,-30.164 30.607,-6.706 ; 29.845,-12.192 29.845,-4.801 ; 31.115,-7.493 31.115,-4.801 cw(c33.813,-4.801) 31.905,-2.893 32.484,-2.314 cw(c34.392,-4.222) 34.392,-1.524 36.195,-1.524 ; 32.258,-0.127 ccw(c32.258,-0.434) 32.041,-0.217 31.803,-0.455 cw(c31.369,-0.022) 31.369,-0.635 31.75,-0.254 cw(c31.443,-0.561) 31.877,-0.561 31.877,-1.016 ccw(c32.044,-1.016) 31.926,-1.134 32.731,-1.94 cw(c33.122,-2.33) 33.122,-1.778 ccw(c33.122,-4.476) 31.214,-2.568 30.734,-3.048 cw(c29.508,-1.822) 29.508,-3.556 29.464,-3.556 29.464,-3.302 cw(c30.69,-3.302) 29.823,-2.435 30.92,-1.338 cw(c31.391,-1.809) 31.391,-1.143 ccw(c31.391,-0.276) 32.004,-0.889 cw(c32.311,-1.196) 32.311,-0.762 34.618,-0.762 ccw(c34.618,-0.328) 34.925,-0.635 ccw(c35.538,-0.022) 35.538,-0.889 36.322,-0.889 35.241,-0.889 ccw(c35.241,-2.877) 33.835,-1.471 cw(c33.401,-1.038) 33.401,-1.651 cw(c33.401,-0.425) 32.534,-1.292 32.258,-1.016 32.385,-1.016 33.02,-0.381 34.417,-0.381 cw(c32.884,-0.381) 33.968,-1.465 33.81,-1.623 cw(c31.902,0.285) 31.902,-2.413 30.988,-2.413 cw(c30.681,-2.413) 30.898,-2.63 30.607,-2.921 ccw(c31.22,-3.534) 30.353,-3.534 30.353,-4.572 30.353,-5.334 ccw(c30.353,-5.641) 30.136,-5.424 29.845,-5.715 29.845,-4.55 cw(c30.712,-4.55) 30.099,-3.937 30.099,-3.429 cw(c31.632,-3.429) 30.548,-2.345 32.738,-0.155 cw(c34.646,-2.063) 34.646,0.635 35.687,0.635 ; 32.258,0.889 34.947,0.889 cw(c34.947,0.022) 35.56,0.635 ; 34.299,1.016 51.079,1.016 cw(c51.079,-1.682) 52.987,0.226 53.049,0.164 ccw(c53.467,0.582) 53.467,-0.009 cw(c52.263,-0.009) 53.114,-0.861 cw(c51.206,1.047) 51.206,-1.651 49.022,-1.651 ; 34.519,0.635 50.825,0.635 cw(c50.825,-2.063) 52.733,-0.155 52.536,-0.353 cw(c50.628,1.555) 50.628,-1.143 35.919,-1.143 ; 34.646,0.127 Q1.1@52.959,0.127 ; 34.671,0.889 ccw(c34.978,1.196) 34.978,0.762 47.625,0.762 ; 35.662,-0.381 51.816,-0.381 ; 35.789,-1.524 50.063,-1.524 ccw(c50.063,1.174) 51.971,-0.734 Q1.1@52.578,-0.127 ; 35.789,-0.381 Q1.1@52.451,-0.381 ; 36.932,-0.508 Q1.1@52.451,-0.508 ; 36.932,-0.254 50.546,-0.254
NetQ2_1: Q2.1 R6.2 | length 262.8
  Bottom Layer w1: 4.445,-2.286 4.445,0.35 cw(c5.746,0.35) 4.826,1.27 cw(c5.439,0.657) 5.439,1.524 cw(c5.439,0.858) 5.91,1.329 cw(c5.461,0.88) 6.096,0.88 6.096,-1.143 ccw(c7.016,-2.063) 5.715,-2.063 5.715,-2.667 ; Q2.1@4.953,-0.508 4.953,-24.409 ccw(c7.651,-24.409) 5.743,-26.317 7.338,-27.912 cw(c5.43,-29.82) 8.128,-29.82 8.128,-35.966 ccw(c10.826,-35.966) 8.918,-37.874 R6.2@11.811,-40.767 ; Q2.1@4.953,0.254 ccw(c6.793,-1.586) 4.191,-1.586 4.191,-21.844 4.191,-24.028 ccw(c6.889,-24.028) 4.981,-25.936 7.592,-28.547 cw(c5.684,-30.455) 8.382,-30.455 8.382,-36.093 ccw(c11.08,-36.093) 9.172,-38.001 11.848,-40.677 cw(c11.631,-40.894) R6.2@11.938,-40.894 ; Q2.1@5.218,-0.254 5.218,-23.404 ccw(c7.916,-23.404) 6.008,-25.312 8.354,-27.658 cw(c6.446,-29.566) 9.144,-29.566 9.144,-37.084 ; Q2.1@5.588,0.127 5.588,-22.885 ccw(c8.286,-22.885) 6.378,-24.793 8.481,-26.896 cw(c6.573,-28.804) 9.271,-28.804 9.271,-36.601 ccw(c11.969,-36.601) 10.061,-38.509 R6.2@11.684,-40.132 ; 5.715,-26.543 6.957,-27.785 cw(c5.049,-29.693) 7.747,-29.693 7.747,-37.363 ccw(c10.445,-37.363) 8.537,-39.271 10.132,-40.866 ccw(c12.04,-38.958) 12.04,-41.656 12.139,-41.656 ccw(c12.139,-41.222) R6.2@12.446,-41.529 ; Q2.1@5.842,0.127 cw(c4.922,-0.793) 6.223,-0.793 6.223,-22.934 ccw(c6.657,-22.934) 6.35,-23.241 ccw(c8.496,-23.241) 6.979,-24.759 8.608,-26.388 cw(c6.7,-28.296) 9.398,-28.296 9.398,-36.474 ccw(c12.096,-36.474) 10.188,-38.382 R6.2@12.446,-40.64 ; 7.366,-27.432 ccw(c8.286,-27.432) 7.635,-28.082 8.673,-29.12 ccw(c8.89,-28.903) 8.89,-29.21 ; 8.001,-37.109 ccw(c10.699,-37.109) 8.791,-39.017 10.005,-40.231 ccw(c11.913,-38.323) 11.913,-41.021 R6.2@12.192,-41.021 ; 8.382,-35.814 8.382,-36.855 ccw(c11.08,-36.855) 9.172,-38.763 9.652,-39.243 ; 9.017,-36.728 ccw(c11.715,-36.728) 9.807,-38.636 R6.2@12.319,-41.148 ; 9.271,-36.728 ccw(c11.969,-36.728) 10.061,-38.636 R6.2@11.938,-40.513 ; 10.389,-40.64 R6.2@12.065,-40.64
NetQ2_3: Q2.3 Q.2 R7.2 R8.2 R9.2 R10.2 | length 476
  Bottom Layer w1: Q2.3@15.367,0.381 15.72,0.734 cw(c17.628,-1.174) 17.628,1.524 20.853,1.524 cw(c20.853,-1.174) 22.761,0.734 23.848,-0.353 cw(c21.94,-2.261) 24.638,-2.261 24.638,-6.223 ; Q2.3@15.875,-0.381 16.101,-0.155 cw(c18.009,-2.063) 18.009,0.635 20.726,0.635 cw(c20.726,-2.063) 22.634,-0.155 23.848,-1.369 cw(c21.94,-3.277) 24.638,-3.277 24.638,-12.468 cw(c23.771,-12.468) 24.384,-13.081 ccw(c24.691,-13.388) R7.2@24.257,-13.388 ; Q2.3@15.875,-0.254 20.726,-0.254 cw(c20.726,-2.952) 22.634,-1.044 23.721,-2.131 cw(c21.813,-4.039) 24.511,-4.039 24.511,-30.861 24.511,-33.807 ccw(c27.209,-33.807) 25.301,-35.715 25.372,-35.786 ccw(c27.28,-33.878) 27.28,-36.576 33.909,-36.576 37.911,-36.576 cw(c37.911,-39.178) 39.751,-37.338 39.751,-39.392 ccw(c40.618,-39.392) Q.2@40.005,-40.005 ; Q2.3@16.002,-0.889 18.821,-0.889 cw(c18.821,-3.587) 20.729,-1.679 23.213,-4.163 cw(c21.305,-6.071) 24.003,-6.071 24.003,-28.47 ccw(c24.87,-28.47) 24.257,-29.083 ; Q2.3@16.256,-1.016 17.297,-1.016 cw(c17.297,-3.714) 19.205,-1.806 21.943,-4.544 cw(c20.035,-6.452) 22.733,-6.452 22.733,-30.378 ccw(c25.431,-30.378) 23.523,-32.286 23.876,-32.639 ; Q2.3@16.256,-0.381 19.329,-0.381 cw(c19.329,-3.079) 21.237,-1.171 23.594,-3.528 cw(c21.686,-5.436) 24.384,-5.436 24.384,-9.144 ; Q2.3@16.383,-0.381 19.837,-0.381 cw(c19.837,-3.079) 21.745,-1.171 23.721,-3.147 cw(c21.813,-5.055) 24.511,-5.055 24.511,-8.509 ; Q2.3@16.764,-0.889 17.932,-0.889 cw(c17.932,-3.587) 19.84,-1.679 22.959,-4.798 cw(c21.051,-6.706) 23.749,-6.706 23.749,-29.347 ; Q2.3@17.145,0 18.821,0 cw(c18.821,-2.698) 20.729,-0.79 22.324,-2.385 cw(c20.416,-4.293) 23.114,-4.293 23.114,-32.664 ccw(c25.812,-32.664) 23.904,-34.572 24.737,-35.405 ccw(c26.645,-33.497) 26.645,-36.195 37.363,-36.195 cw(c37.363,-38.893) 39.271,-36.985 39.497,-37.211 36.405,-37.211 cw(c36.405,-35.477) 35.179,-36.703 ccw(c33.953,-37.929) 33.953,-36.195 28.677,-36.195 cw(c28.677,-33.497) 26.769,-35.405 25.555,-34.191 cw(c27.463,-32.283) 24.765,-32.283 24.765,-28.479 ccw(c23.464,-28.479) 24.384,-27.559 24.384,-22.584 ccw(c23.517,-22.584) R9.2@24.13,-21.971 ; 22.86,-31.496 22.86,-32.664 ccw(c25.558,-32.664) 23.65,-34.572 24.892,-35.814 ; R8.2@23.749,-27.432 23.749,-34.609 ccw(c26.351,-34.609) 24.511,-36.449 34.82,-36.449 cw(c34.82,-37.316) 35.433,-36.703 ; R8.2@24.13,-27.178 24.13,-31.394 ccw(c26.828,-31.394) 24.92,-33.302 26.769,-35.151 ccw(c28.677,-33.243) 28.677,-35.941 38.038,-35.941 cw(c38.038,-38.543) 39.878,-36.703 cw(c39.265,-37.316) 40.132,-37.316 Q.2@40.132,-39.751 ; R8.2@24.13,-27.051 24.13,-35.096 ccw(c25.864,-35.096) 24.638,-36.322 ccw(c26.478,-34.482) 26.478,-37.084 38.831,-37.084 cw(c38.831,-38.385) 39.751,-37.465 ; 24.384,-32.766 24.384,-8.255 cw(c24.511,-8.255) 24.511,-8.128 ; R8.2@24.384,-27.178 24.384,-35.712 ccw(c25.502,-35.712) 25.502,-36.83 38.76,-36.83 cw(c38.76,-37.948) 39.878,-37.948 Q.2@39.878,-40.132 ; R8.2@24.511,-27.305 cw(c23.591,-28.225) 24.892,-28.225 24.892,-32.537 ccw(c27.59,-32.537) 25.682,-34.445 26.797,-35.56 ; R8.2@24.638,-27.559 24.638,-33.299 ccw(c27.336,-33.299) 25.428,-35.207 25.88,-35.659 ccw(c27.788,-33.751) 27.788,-36.449 38.525,-36.449 cw(c38.525,-38.183) 39.751,-36.957 cw(c39.138,-37.57) 40.005,-37.57 Q.2@40.005,-39.751 ; 36.576,-36.83 37.49,-36.83 cw(c37.49,-39.528) 39.398,-37.62 39.571,-37.793 cw(c39.138,-38.227) 39.751,-38.227
NetQ5_1: Q5.1 Q6.2 | length 71.7
  Bottom Layer w1: Q5.1@85.598,-13.462 85.598,-13.44 cw(c86.465,-13.44) 85.852,-12.827 ccw(c86.159,-12.52) 86.159,-12.954 91.843,-12.954 cw(c91.843,-13.821) 92.456,-13.208 ccw(c93.069,-13.208) 92.636,-13.642 93.091,-14.097 ; Q5.1@85.979,-13.462 cw(c86.899,-14.382) 86.899,-13.081 91.865,-13.081 cw(c91.865,-14.815) 93.091,-13.589 93.711,-14.209 cw(c93.06,-14.859) 93.98,-14.859 ; Q5.1@85.979,-13.208 88.033,-13.208 ccw(c88.033,-12.341) 88.646,-12.954 ; Q5.1@86.106,-13.462 ccw(c85.493,-12.849) 86.36,-12.849 90.551,-12.849 cw(c90.551,-13.208) 90.805,-12.954 ; Q5.1@86.106,-13.335 91.059,-13.335 cw(c91.059,-16.401) 93.227,-14.233 93.382,-14.388 cw(c93.165,-14.605) 93.472,-14.605 ccw(c93.779,-14.605) 93.562,-14.822 ; Q5.1@86.36,-13.335 92.329,-13.335 cw(c92.329,-14.351) 92.875,-13.494 cw(c92.329,-14.351) 93.345,-14.351 ccw(c94.361,-14.351) 94.361,-15.367 96.774,-15.367 Q6.2@96.012,-15.367 ; 87.78,-13.208 ccw(c87.78,-14.509) Q5.1@86.86,-13.589 ; 88.086,-13.081 ccw(c88.086,-14.815) Q5.1@86.86,-13.589 ; 88.138,-13.335 90.805,-13.335 cw(c90.805,-16.401) 92.973,-14.233 93.209,-14.469 ccw(c95.377,-12.301) 95.377,-15.367 Q6.2@96.012,-15.367 ; 88.393,-12.954 ccw(c88.393,-15.122) Q5.1@86.86,-13.589 ; 88.647,-12.849 ccw(c88.647,-15.376) Q5.1@86.86,-13.589 ; 89.281,-13.208 91.313,-13.208 cw(c91.313,-16.274) 93.481,-14.106 93.844,-14.469 ccw(c96.012,-12.301) Q6.2@96.012,-15.367 ; Q5.1@86.86,-13.589 cw(c87.473,-14.202) 87.473,-13.335 ; Q5.1@86.86,-13.589 cw(c87.473,-14.202) 87.473,-13.335 ; Q5.1@86.86,-13.589 cw(c87.473,-14.202) 87.473,-13.335 ; Q5.1@86.86,-13.589 cw(c87.473,-14.202) 87.473,-13.335 ; Q5.1@86.86,-13.589 cw(c87.473,-14.202) 87.473,-13.335 ; Q5.1@86.86,-13.589 cw(c87.473,-14.202) 87.473,-13.335
NetQ_3: Q.1 R5.2 R6.1 | length 83.7
  Bottom Layer w1: R6.1@22.352,-41.656 23.337,-40.671 cw(c24.638,-41.972) 24.638,-40.132 cw(c24.945,-40.439) 24.945,-40.005 36.387,-40.005 cw(c36.387,-42.607) Q.1@38.227,-40.767 ; R6.1@22.352,-40.894 22.352,-40.869 cw(c23.47,-40.869) 23.47,-39.751 Q.1@38.227,-39.751 ; R5.2@22.479,-46.609 cw(c22.479,-46.228) 22.098,-46.228 22.098,-40.869 cw(c23.216,-40.869) 23.216,-39.751 29.083,-39.751 ; R5.2@22.606,-46.482 ccw(c22.606,-46.175) 22.823,-46.392 ccw(c21.507,-45.076) 23.368,-45.076 23.368,-43.04 cw(c26.403,-43.04) 24.257,-40.894 cw(c25.483,-42.12) 25.483,-40.386 36.874,-40.386 cw(c36.874,-42.12) 38.1,-40.894 ; R5.2@22.733,-46.228 22.733,-42.774 cw(c25.431,-42.774) 23.523,-40.866 23.848,-40.541 cw(c25.756,-42.449) 25.756,-39.751 34.29,-39.751
NetR2_1: R2.1 U.1 | length 29
  Bottom Layer w1: R2.1@29.464,-42.291 29.464,-48.588 ccw(c29.898,-48.588) U.1@29.591,-48.895 ; U.1@29.845,-48.768 ccw(c28.619,-47.542) 30.353,-47.542 R2.1@30.353,-42.164 ; U.1@29.972,-49.276 R2.1@29.972,-42.291 ; R2.1@29.972,-42.672 cw(c29.052,-43.592) 30.353,-43.592 U.1@30.353,-48.895 ; U.1@30.099,-49.276 30.099,-46.965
